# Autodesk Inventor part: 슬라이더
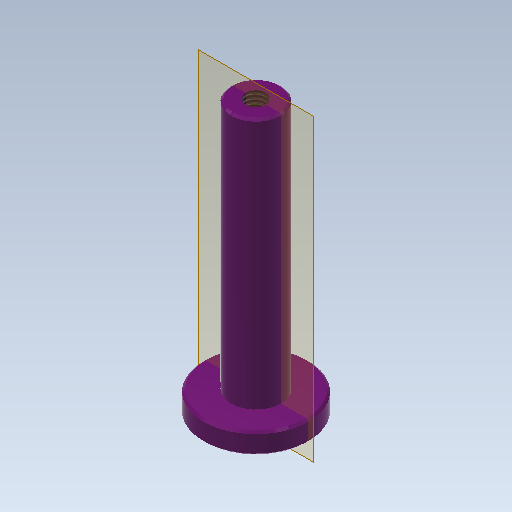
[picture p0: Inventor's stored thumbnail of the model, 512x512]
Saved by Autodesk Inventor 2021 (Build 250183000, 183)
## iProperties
Created: 2016-02
Part Number: 슬라이더
Material: 스테인리스강
Document SubType Name: Modeling
Designer: mduedu
Density: 8.08 g/cm^3
Appearance: 매끄러움 - 자주색
Author: mduedu
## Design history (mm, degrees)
sketch "스케치1"
  geometry: C1 r 12.5 at (0, 0); 1 further point
  constraints: 1 centre point, 1 coincident
  dimensions: "d0" = 25 diameter of C1
extrude "돌출1" new body sketch "스케치1" distance "d1" = 5; taper "d2" = 0 deg
sketch "스케치2"
  geometry: C1 r 6 at (0, 0); 1 further point
  constraints: 1 centre point, 1 coincident
  dimensions: "d3" = 12 diameter of C1
extrude "돌출2" join sketch "스케치2" distance "d4" = 60; taper "d5" = 0 deg
chamfer "모따기1" distance "d6" = 0.5; stored, may be unused: second distance "d7" = 2, angle "d8" = 45 deg
hole "구멍1" diameter "d11" = 4.917; stored, may be unused: countersink angle "d15" = 90 deg, drill point angle "d17" = 118 deg; dims "d9" = 10, "d10" = 10, "d12" = 10, "d13" = 4, "d14" = 2, "d16" = 12
chamfer "모따기2" distance "d18" = 0.5; stored, may be unused: second distance "d19" = 2, angle "d20" = 45 deg
node "솔리드1"
